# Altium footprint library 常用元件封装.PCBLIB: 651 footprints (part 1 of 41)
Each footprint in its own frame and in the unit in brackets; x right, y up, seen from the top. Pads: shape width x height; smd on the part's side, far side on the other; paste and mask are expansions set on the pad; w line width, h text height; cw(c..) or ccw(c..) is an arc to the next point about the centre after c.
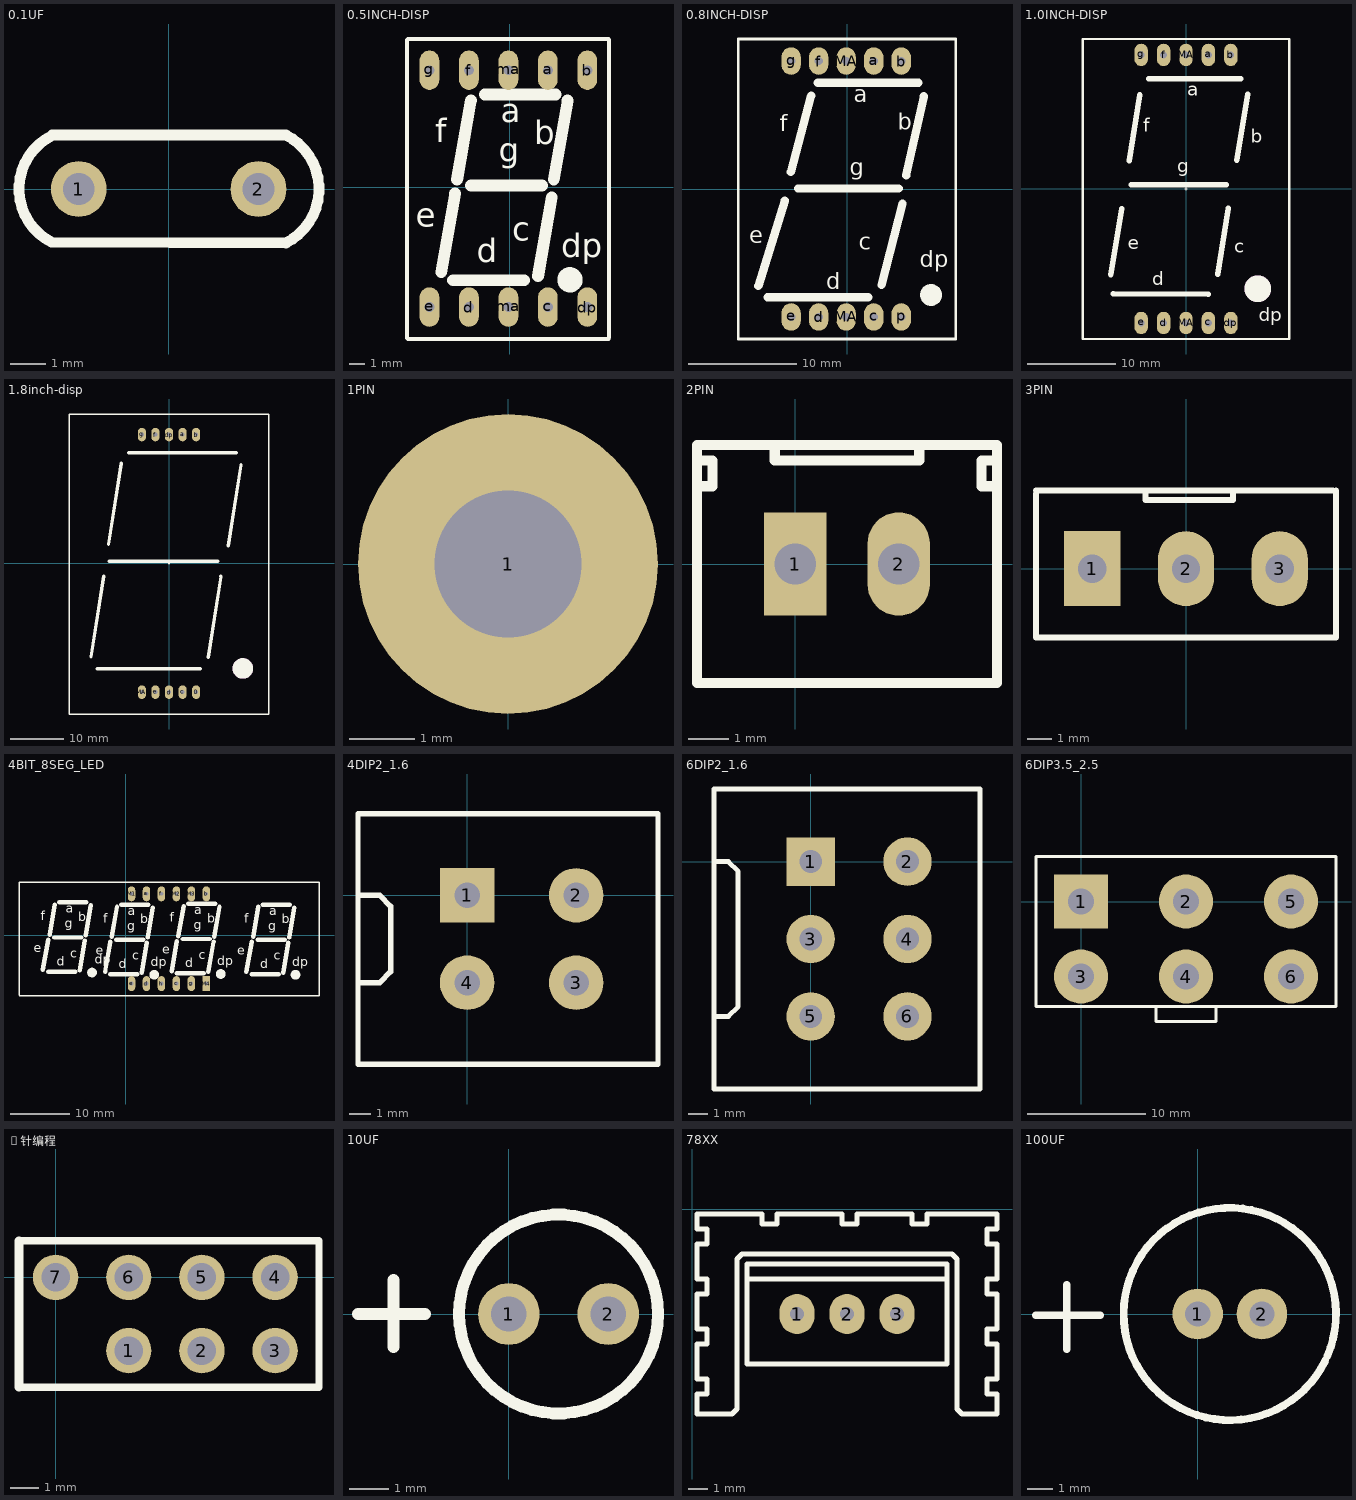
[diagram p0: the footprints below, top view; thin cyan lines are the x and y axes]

## 0.1UF [mil]
pads (2):
  round 62 hole 35.43: 1(-100,0) 2(100,0)
TopLayer:
  text "CD4000系列IC" at -120,100 h60
TopOverlay:
  lines w12: -130.04,59.28 ccw(c-100,0) -130.04,-59.28 130.54,-59.99 ccw(c100,0) 130.54,59.99 -129.42,60.22

## 0.5INCH-DISP [mil]
pads (10):
  oval 50x100 hole 25: a(97,297) b(197,297) c(97,-303) d(-103,-303) dp(197,-303) e(-203,-303) f(-103,297) g(-203,297) ma(-3,-303) ma(-3,297)
TopOverlay:
  circle w40: c153,-234 r12
  lines w10: -260,-382 -260,374 ; -258,-384 251,-384 ; -258,376 251,376 ; 252,-380 252,374
  lines w30: -173,-215 -138,-15 ; -143,-235 37,-235 ; -133,20 -98,220 ; -98,5 82,5 ; -63,235 117,235 ; 72,-225 107,-25 ; 112,20 147,220
  text "c" at 7,-135 h60
  text "dp" at 131,-177 h60
  text "e" at -238,-100 h60
  text "d" at -83,-190 h60
  text "a" at -23,165 h60
  text "g" at -28,65 h60
  text "b" at 62,110 h60
  text "f" at -188,115 h60

## 0.8INCH-DISP [mil]
pads (10):
  oval 70x100 hole 30: a(97,465) b(197,465) c(97,-465) d(-103,-465) e(-203,-465) f(-103,465) g(-203,465) MA(-3,-465) MA(-3,465) p(197,-465)
TopOverlay:
  circle w40: c305.31,-385 r19.68
  lines w10: -395,-545 -395,545 395,545 395,-545 -395,-545
  lines w30: -322,-352 -226,-42 ; -289,-393 77.14,-393 ; -204,62 -130,339 ; -177.68,2.24 188.47,2.24 ; -108,-478 -103,-473 ; -106.14,386 260,386 ; 125,-349 202,-53 ; 215,49 279,337
  text "a" at 25,315 h60
  text "g" at 10,50 h60
  text "c" at 43,-220 h60
  text "d" at -75,-365 h60
  text "e" at -355,-198 h60
  text "f" at -245,210 h60
  text "dp" at 265,-285 h60
  text "b" at 185,215 h60

## 1.0INCH-DISP [mil]
pads (10):
  oval 60x100 hole 30: a(100,598) b(200,598) c(100,-598) d(-100,-598) dp(200,-598) e(-200,-598) f(-100,598) g(-200,598) MA(0,-598) MA(0,598)
TopOverlay:
  lines w2: -6,0 6,0 ; 0,-6 0,5
  lines w10: -461,-10 -461,10 ; -460.88,-669.58 -460.88,669 ; -459.88,-669.58 461,-669.58 461,669 -459.88,669
  lines w25: -335,-382 -287,-89 ; -324,-467 99,-470 ; -254,126 -206,419 ; -244,19 179,19 ; -167,492 245,492 ; 141,-380 189,-87 ; 227,129 275,422
  text "g" at -40,75 h60
  text "dp" at 325,-590 h60
  text "f" at -190,255 h60
  text "e" at -260,-270 h60
  text "d" at -150,-430 h60
  text "c" at 215,-285 h60
  text "b" at 290,205 h60
  text "a" at 5,415 h60
TopOverlay keep-out:
  circle w100: c320.57,-445 r9.43

## 1.8inch-disp [mil]
pads (10):
  oval 60x100 hole 30: 0(200,-950) a(100,950) b(200,950) c(100,-950) d(0,-950) dp(0,950) e(-100,-950) f(-100,950) g(-200,950) MA(-200,-950)
TopOverlay:
  lines w2: -5,0 5,0 ; 0,-5 0,4
  lines w10: -736,-1111 -736,1101.6 736,1101.6 736,-1111 -736,-1111
  lines w25: -575,-691 -481,-93 ; -528,-778 230,-778 ; -446,139 -352,737 ; -442,15 359,15 ; -299,815 496,815 ; 289,-694 383,-96 ; 437,128 531,726
TopOverlay keep-out:
  circle w100: c544.39,-775 r25.61

## 1PIN [mil]
pads (1):
  round 180 hole 88: 1(0,0)

## 2PIN [mil]
pads (2):
  rect 60x100 hole 40: 1(0,0)
  oval 60x100 hole 40: 2(100,0)
TopOverlay:
  lines w10: -95,75 -80,75 -80,100 -95,100 ; -20,115 -20,100 120,100 120,115 ; 135,-115 195,-115 ; 195,75 180,75 180,100 195,100 ; 195,-115 -95,-115 -95,115 195,115 195,-115

## 3PIN [mil]
pads (3):
  rect 90x120 hole 45: 1(-150,0)
  oval 90x120 hole 45: 2(0,0) 3(150,0)
TopOverlay:
  lines w10: -240,120 -240,-110 240,-110 ; -240,125 235,125 ; -65,125 -65,110 75,110 75,125 ; -10,-110 240,-110 ; 240,125 240,-110

## 4BIT_8SEG_LED [mil]
pads (12):
  oval 50x100 hole 25: a(137,277) b(537,277) c(337,-323) d(137,-323) e(37,-323) f(237,277) g(437,-323) h(237,-323) M1(37,277) M2(337,277) M3(437,277)
  rect 50x100 hole 25: M4(537,-323)
TopOverlay:
  circle w40: c1133,-264 r12
  circle w40: c633,-259 r12
  circle w40: c-227,-249 r12
  circle w40: c188,-264 r12
  lines w10: -715,-405 1290,-405 ; -715,-401 -715,355 1290,355 1290,-404
  lines w30: -555,-230 -520,-30 ; -520,-245 -340,-245 ; -510,5 -475,205 ; -480,-15 -300,-15 ; -445,220 -265,220 ; -310,-235 -275,-35 ; -270,0 -235,200 ; -140,-245 -105,-45 ; -105,-260 75,-260 ; -95,-10 -60,190 ; -65,-30 115,-30 ; -30,205 150,205 ; 105,-250 140,-50 ; 145,-15 180,185 ; 305,-240 340,-40 ; 340,-255 520,-255 ; 350,-5 385,195 ; 380,-25 560,-25 ; 415,210 595,210 ; 550,-245 585,-45 ; 590,-10 625,190 ; 805,-245 840,-45 ; 840,-260 1020,-260 ; 850,-10 885,190 ; 880,-30 1060,-30 ; 915,205 1095,205 ; 1050,-250 1085,-50 ; 1090,-15 1125,185
  text "f" at 792,85 h60
  text "b" at 1042,80 h60
  text "g" at 952,35 h60
  text "a" at 957,135 h60
  text "d" at 897,-220 h60
  text "e" at 742,-130 h60
  text "dp" at 1111,-207 h60
  text "c" at 987,-165 h60
  text "f" at 292,90 h60
  text "b" at 542,85 h60
  text "g" at 452,40 h60
  text "a" at 457,140 h60
  text "d" at 397,-215 h60
  text "e" at 242,-125 h60
  text "dp" at 611,-202 h60
  text "c" at 487,-160 h60
  text "f" at -568,100 h60
  text "b" at -318,95 h60
  text "g" at -408,50 h60
  text "a" at -403,150 h60
  text "d" at -463,-205 h60
  text "e" at -618,-115 h60
  text "dp" at -209,-192 h60
  text "c" at -373,-150 h60
  text "f" at -153,85 h60
  text "b" at 97,80 h60
  text "g" at 7,35 h60
  text "a" at 12,135 h60
  text "d" at -48,-220 h60
  text "e" at -203,-130 h60
  text "dp" at 166,-207 h60
  text "c" at 42,-165 h60

## 4DIP2_1.6 [mil]
pads (4):
  rect 100x100 hole 47: 1(0,0)
  round 100 hole 47: 2(200,0) 3(200,-160) 4(0,-160)
TopOverlay:
  lines w10: -200,-160 -160,-160 -140,-140 -140,-20 -160,0 -200,0 ; -200,-310 350,-310 350,150 -200,150 -200,-310

## 6DIP2_1.6 [mil]
pads (6):
  rect 100x100 hole 47: 1(0,0)
  round 100 hole 47: 2(200,0) 3(0,-160) 4(200,-160) 5(0,-320) 6(200,-320)
TopOverlay:
  lines w10: -200,-320 -170,-320 -150,-300 -150,-20 -170,0 -200,0 ; -200,-470 -200,150 -150,150 350,150 350,-470 -150,-470 -200,-470

## 6DIP3.5_2.5 [mil]
pads (6):
  rect 180x180 hole 88: 1(0,0)
  round 180 hole 88: 2(350,0) 3(0,-250) 4(350,-250) 5(700,0) 6(700,-250)
TopOverlay:
  lines w10: 250,-350 250,-400 450,-400 450,-350 ; 350,150 -150,150 ; -150,150 -150,-350 850,-350 850,150 -150,150

## 7针编程 [mil]
pads (7):
  round 62 hole 39: 1(100,-100) 2(200,-100) 3(300,-100) 4(300,0) 5(200,0) 6(100,0) 7(0,0)
TopOverlay:
  lines w10: -50,-150 360,-150 360,50 -50,50
  lines w12: -50,-150 -50,50

## 10UF [mil]
pads (2):
  round 62 hole 35.43: 1(0,0) 2(100,0)
TopOverlay:
  circle w12: c50,0 r100
  lines w12: -151.69,0 -84.17,0 ; -115.87,-33.27 -115.87,34.25

## 78XX [mil]
pads (3):
  oval 70x80 hole 28: 1(210,-210) 2(310,-210) 3(410,-210)
TopOverlay:
  lines w10: 110,-140 510,-140 ; 10,-410 80,-410 90,-400 90,-100 100,-90 520,-90 530,-100 530,-400 540,-410 560,-410 610,-410 610,-370 590,-370 590,-340 610,-340 610,-270 590,-270 590,-240 610,-240 610,-170 590,-170 590,-140 610,-140 610,-70 590,-70 590,-40 610,-40 610,-10 470,-10 470,-30 440,-30 440,-10 330,-10 330,-30 300,-30 300,-10 170,-10 170,-30 140,-30 140,-10 10,-10 10,-40 30,-40 30,-70 10,-70 10,-140 30,-140 30,-170 10,-170 10,-240 30,-240 30,-270 10,-270 10,-340 30,-340 30,-370 10,-370 10,-410 ; 110,-310 510,-310 510,-110 110,-110 110,-310

## 100UF [mm]
pads (2):
  round 2 hole 1: 1(0,0) 2(2.54,0)
TopOverlay:
  lines w0.305: -6.395,-0.05 -3.855,-0.05 ; -5.175,-1.395 -5.175,1.145 ; 5.049,-1.834 cw(c1.27,0) 5.129,-1.658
